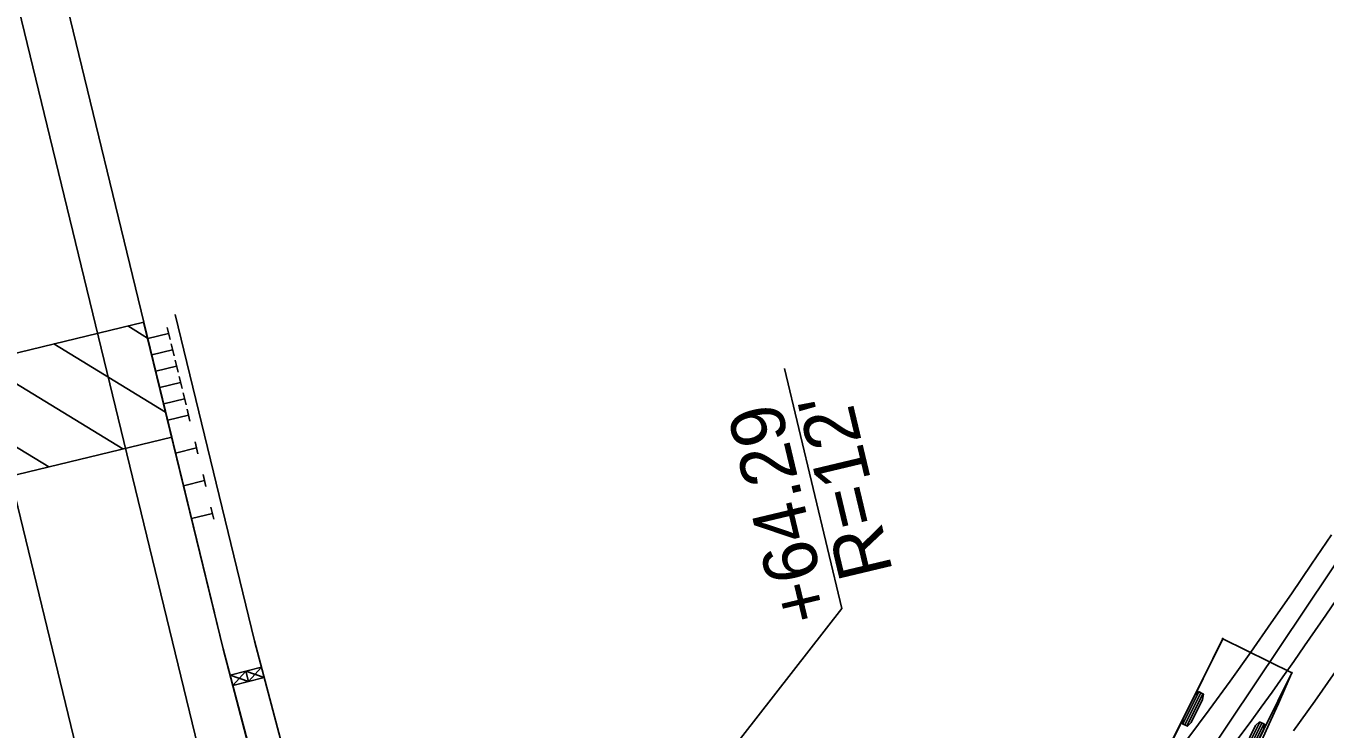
# Model space of a CAD drawing. Extents: x 1735795 to 1737428, y 699740 to 701024.
# Drawn here: x 1736230.5 to 1736351.1, y 700401.5 to 700466.8 of the extents above; entities that cross this region are included whole.
import ezdxf

# ---------------------------------------------------------------- set-up
doc = ezdxf.new("R2010")
doc.units = 0
for name, color, linetype in [('Prop Approach Slab', 7, 'Continuous'), ('Prop Approach Slab Hatching', 7, 'Continuous'), ('Prop Conc Shoulder Berm Gutter', 7, 'Continuous'), ('Prop Dimension', 7, 'Continuous'), ('Prop Dimension Text', 7, 'Continuous'), ('Prop EOT', 7, 'Continuous'), ('Prop Guardrail', 7, 'Continuous'), ('Prop Guardrail Anchor Unit CELL', 7, 'Continuous'), ('Prop Horizontal Alignment', 7, 'Continuous'), ('Prop Paved Shoulder', 7, 'Continuous'), ('Prop Roadway Bridge', 7, 'Continuous'), ('Prop Structure Anchor Unit CELL', 7, 'Continuous'), ('Scratch_Level_1', 7, 'Continuous'), ('Scratch_Level_2', 7, 'Continuous'), ('Scratch_Level_4', 7, 'Continuous'), ('Scratch_Level_5', 7, 'Continuous')]:
    doc.layers.add(name, color=color, linetype=linetype)

msp = doc.modelspace()

# ---------------------------------------------------------------- linework, layer by layer
at = {"layer": 'Prop Approach Slab'}
for p, q in [((1736241.47, 700439.29), (1736211.5, 700432.01)), ((1736244.06, 700428.6), (1736241.47, 700439.29)), ((1736244.06, 700428.6), (1736214.1, 700421.32))]:
    msp.add_line(p, q, dxfattribs=at)
at = {"layer": 'Prop Approach Slab Hatching'}
for p, q in [((1736241.83, 700437.8), (1736239.99, 700438.93)), ((1736243.5, 700430.92), (1736233.12, 700437.26)), ((1736239.52, 700427.5), (1736226.26, 700435.6)), ((1736232.66, 700425.83), (1736219.41, 700433.92))]:
    msp.add_line(p, q, dxfattribs=at)
at = {"layer": 'Prop Conc Shoulder Berm Gutter'}
msp.add_line((1736248.03, 700412.27), (1736241.47, 700439.27), dxfattribs=at)
at = {"layer": 'Prop Dimension'}
msp.add_lwpolyline([(1736264.39, 700358.91), (1736306.26, 700412.7), (1736300.94, 700434.97)], dxfattribs=at)
at = {"layer": 'Prop EOT'}
msp.add_line((1736256.89, 700357.09), (1736211.5, 700543.97), dxfattribs=at)
at = {"layer": 'Prop Guardrail'}
msp.add_line((1736248.84, 700408.94), (1736245.9, 700421.05), dxfattribs=at)
at = {"layer": 'Prop Guardrail Anchor Unit CELL'}
for p, q in [((1736248.84, 700408.94), (1736260.78, 700363.74)), ((1736249.49, 700406.48), (1736252.39, 700407.25)), ((1736249.49, 700406.48), (1736249.74, 700405.52)), ((1736251.19, 700405.9), (1736249.49, 700406.48)), ((1736250.94, 700406.87), (1736249.74, 700405.52)), ((1736249.74, 700405.52), (1736252.64, 700406.28)), ((1736250.94, 700406.87), (1736251.19, 700405.9)), ((1736252.64, 700406.28), (1736250.94, 700406.87)), ((1736251.19, 700405.9), (1736252.39, 700407.25)), ((1736252.39, 700407.25), (1736252.64, 700406.28)), ((1736249.74, 700405.52), (1736251.19, 700405.9))]:
    msp.add_line(p, q, dxfattribs=at)
at = {"layer": 'Prop Horizontal Alignment'}
for p, q in [((1736284.97, 700194.84), (1736200.81, 700541.38)), ((1736319.39, 700367.96), (1736380.98, 700460.03))]:
    msp.add_line(p, q, dxfattribs=at)
at = {"layer": 'Prop Paved Shoulder'}
for p, q in [((1736248.83, 700408.94), (1736241.46, 700439.27)), ((1736261.61, 700360.55), (1736248.83, 700408.94))]:
    msp.add_line(p, q, dxfattribs=at)
at = {"layer": 'Prop Roadway Bridge'}
msp.add_line((1736241.47, 700439.29), (1736220.84, 700524.2), dxfattribs=at)
at = {"layer": 'Prop Structure Anchor Unit CELL'}
for p, q in [((1736241.47, 700439.27), (1736245.9, 700421.05)), ((1736243.65, 700438.78), (1736243.92, 700437.67)), ((1736241.84, 700437.75), (1736243.78, 700438.22)), ((1736242.21, 700436.23), (1736244.15, 700436.71)), ((1736244.02, 700437.26), (1736244.29, 700436.15)), ((1736242.58, 700434.72), (1736244.52, 700435.19)), ((1736244.39, 700435.74), (1736244.66, 700434.63)), ((1736244.76, 700434.23), (1736245.03, 700433.11)), ((1736242.95, 700433.2), (1736244.89, 700433.67)), ((1736245.12, 700432.71), (1736245.4, 700431.59)), ((1736243.32, 700431.68), (1736245.26, 700432.15)), ((1736243.69, 700430.16), (1736245.63, 700430.63)), ((1736245.49, 700431.19), (1736245.76, 700430.08)), ((1736246.23, 700428.15), (1736246.5, 700427.04)), ((1736244.42, 700427.12), (1736246.37, 700427.6)), ((1736245.16, 700424.09), (1736247.1, 700424.56)), ((1736246.97, 700425.12), (1736247.24, 700424)), ((1736247.71, 700422.08), (1736247.98, 700420.97)), ((1736245.9, 700421.05), (1736247.84, 700421.52))]:
    msp.add_line(p, q, dxfattribs=at)
at = {"layer": 'Scratch_Level_1'}
msp.add_lwpolyline([(1736241.47, 700439.27), (1736248.84, 700408.94), (1736261.62, 700360.56)], dxfattribs=at)
at = {"layer": 'Scratch_Level_2'}
msp.add_lwpolyline([(1736244.39, 700439.98), (1736251.75, 700409.68), (1736264.52, 700361.32)], dxfattribs=at)
at = {"layer": 'Scratch_Level_4'}
for points in [[(1736338.4, 700400.61), (1736340.37, 700403.27), (1736342.31, 700405.95), (1736344.23, 700408.64), (1736346.13, 700411.34), (1736348.02, 700414.06), (1736349.88, 700416.79), (1736351.72, 700419.54)], [(1736348.21, 700401.34), (1736350.17, 700404.07), (1736352.11, 700406.82)]]:
    msp.add_lwpolyline(points, dxfattribs=at)
msp.add_arc((1735985.33, 700663.12), 443.73, 318.1062, 332.5324, dxfattribs=at)
at = {"layer": 'Scratch_Level_5'}
for p, q in [((1736341.64, 700409.88), (1736329.97, 700386.36)), ((1736348.04, 700406.7), (1736341.64, 700409.88)), ((1736336.38, 700383.19), (1736348.04, 700406.7)), ((1736339.42, 700404.94), (1736337.94, 700401.96)), ((1736339.61, 700404.85), (1736338.13, 700401.87)), ((1736339.79, 700404.76), (1736338.31, 700401.77)), ((1736345.08, 700402.14), (1736343.6, 700399.15)), ((1736345.27, 700402.04), (1736343.79, 700399.06)), ((1736345.46, 700401.95), (1736343.97, 700398.97))]:
    msp.add_line(p, q, dxfattribs=at)
for points in [[(1736323.53, 700379.05), (1736323.73, 700379.31), (1736324.7, 700380.62), (1736325.66, 700381.93), (1736326.61, 700383.26), (1736327.54, 700384.59), (1736328.45, 700385.94), (1736329.35, 700387.3), (1736330.23, 700388.67), (1736331.1, 700390.05), (1736331.95, 700391.44), (1736332.78, 700392.83), (1736333.6, 700394.24), (1736334.4, 700395.66), (1736335.18, 700397.09), (1736335.95, 700398.52), (1736336.7, 700399.96), (1736337.44, 700401.42), (1736338.16, 700402.88), (1736338.89, 700404.34), (1736339.61, 700405.79), (1736340.33, 700407.25), (1736341.06, 700408.71), (1736341.64, 700409.88)], [(1736329.76, 700373.79), (1736329.96, 700374.07), (1736331, 700375.45), (1736332.02, 700376.83), (1736333.02, 700378.23), (1736334.01, 700379.65), (1736334.98, 700381.07), (1736335.93, 700382.5), (1736336.78, 700383.99), (1736337.54, 700385.53), (1736338.3, 700387.06), (1736339.06, 700388.59), (1736339.82, 700390.12), (1736340.66, 700391.62), (1736341.49, 700393.12), (1736342.3, 700394.63), (1736343.1, 700396.15), (1736343.88, 700397.67), (1736344.64, 700399.21), (1736345.38, 700400.75), (1736346.11, 700402.31), (1736346.82, 700403.87), (1736347.5, 700405.44), (1736348.04, 700406.7)]]:
    msp.add_lwpolyline(points, dxfattribs=at)
for points in [[(1736339.37, 700404.97), (1736339.84, 700404.74), (1736339.77, 700404.25), (1736338.71, 700402.1), (1736338.36, 700401.75), (1736337.89, 700401.98), (1736337.96, 700402.47), (1736339.03, 700404.62)], [(1736345.04, 700402.16), (1736345.5, 700401.93), (1736345.43, 700401.44), (1736344.37, 700399.29), (1736344.02, 700398.94), (1736343.55, 700399.17), (1736343.62, 700399.66), (1736344.69, 700401.81)]]:
    msp.add_lwpolyline(points, close=True, dxfattribs=at)
for centre in [(1736341.64, 700409.88), (1736348.04, 700406.7)]:
    msp.add_circle(centre, 0.0417, dxfattribs=at)

# ---------------------------------------------------------------- texts
at = {"layer": 'Prop Dimension Text'}
for s, p in [('+64.29', (1736305.28, 700411.97)), ("R=12'", (1736311.03, 700416.1))]:
    msp.add_text(s, height=5, rotation=103.4184, dxfattribs=at).set_placement(p)

doc.saveas('drawing.dxf')
